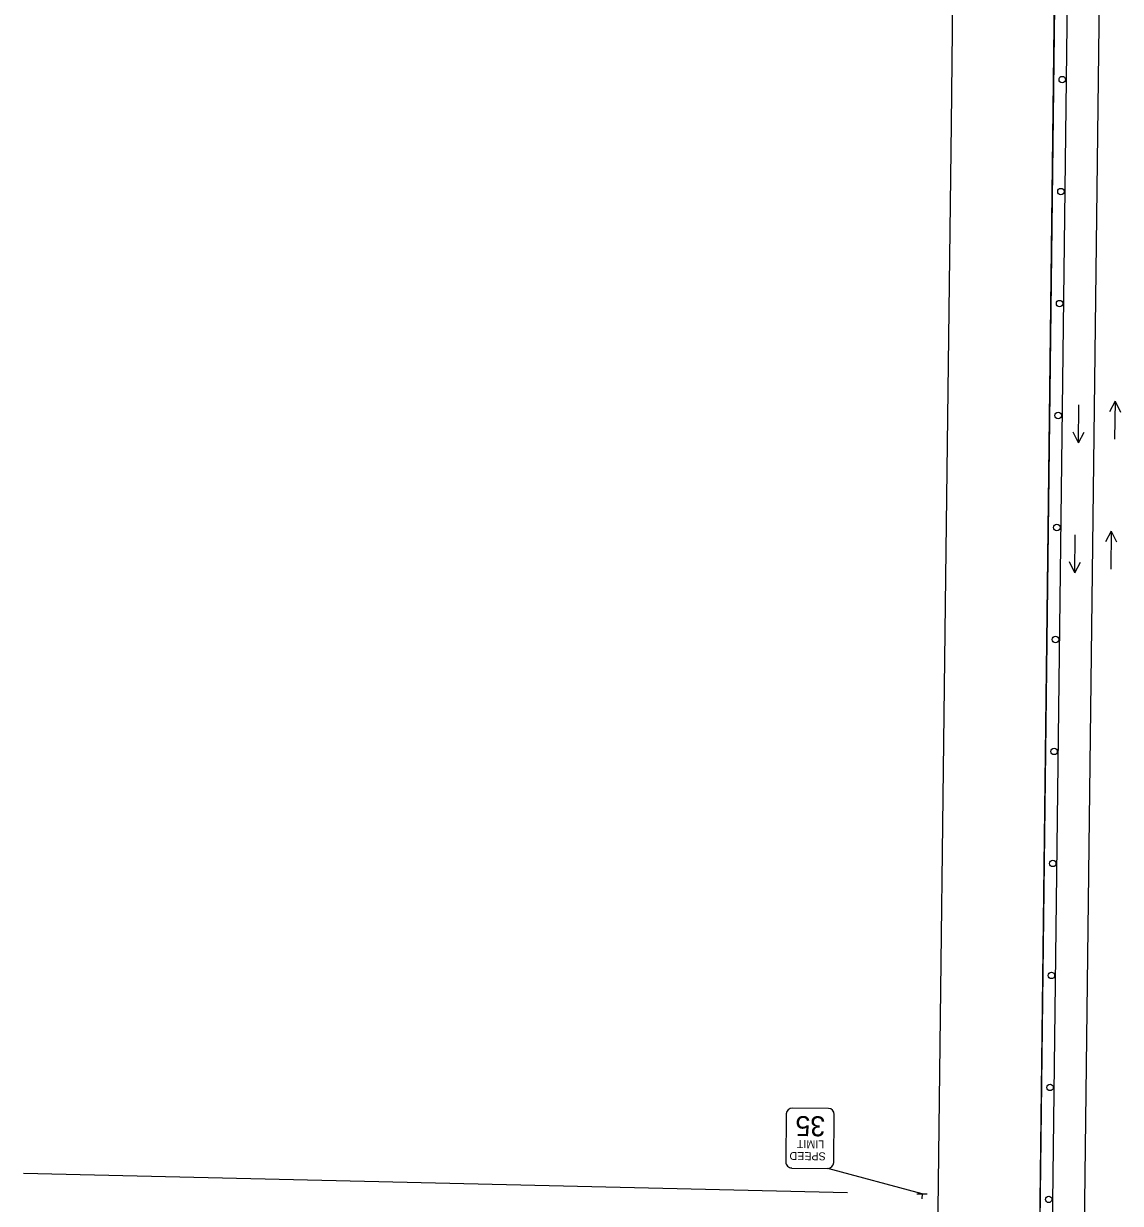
# Model space of a CAD drawing. Extents: x 1651568 to 1653044, y 601329 to 611807.
# Drawn here: x 1652241.2 to 1652584.1, y 607792.4 to 608161.1 of the extents above; entities that cross this region are included whole.
import ezdxf

# ---------------------------------------------------------------- set-up
doc = ezdxf.new("R2010")
doc.units = 0
for name, color, linetype in [('CM_Corridor_Design', 7, 'Continuous'), ('DT_X_Break_Line', 7, 'Continuous'), ('DT_X_Contour_Major', 7, 'Continuous'), ('GE_P_Alignment_500_Cardinal_Points', 7, 'Continuous'), ('MD_P_Drive_MatchLine', 7, 'Continuous'), ('PF_P_Grade_Line_RT', 7, 'Continuous'), ('PF_X_Ground_Line', 7, 'Continuous'), ('PV_P_EOP', 7, 'Continuous'), ('PV_X_EOP', 7, 'Continuous')]:
    doc.layers.add(name, color=color, linetype=linetype)

msp = doc.modelspace()

# ---------------------------------------------------------------- linework, layer by layer
at = {"layer": 'CM_Corridor_Design'}
for p, q in [((1652570.95, 608030.08), (1652571.08, 608041.94)), ((1652582.37, 608043.1), (1652580.61, 608039.74)), ((1652582.37, 608043.1), (1652582.24, 608031.24)), ((1652582.37, 608043.1), (1652584.05, 608039.71)), ((1652570.95, 608030.08), (1652569.27, 608033.47)), ((1652570.95, 608030.08), (1652572.71, 608033.44)), ((1652569.81, 607989.48), (1652569.94, 608001.34)), ((1652581.15, 608002.5), (1652579.39, 607999.14)), ((1652581.15, 608002.5), (1652581.02, 607990.64)), ((1652581.15, 608002.5), (1652582.84, 607999.11)), ((1652569.81, 607989.48), (1652568.13, 607992.87)), ((1652569.81, 607989.48), (1652571.57, 607992.83))]:
    msp.add_line(p, q, dxfattribs=at)
at = {"layer": 'DT_X_Break_Line'}
for centre in [(1652565.87, 608143.61), (1652565.45, 608108.61), (1652565.03, 608073.62), (1652564.61, 608038.62), (1652564.18, 608003.62), (1652563.76, 607968.62), (1652563.34, 607933.63), (1652562.91, 607898.63), (1652562.49, 607863.63), (1652562.07, 607828.63), (1652561.65, 607793.64)]:
    msp.add_circle(centre, 1, dxfattribs=at)
at = {"layer": 'DT_X_Contour_Major'}
msp.add_line((1652551.76, 607199.34), (1652567.38, 608491.59), dxfattribs=at)
for points in [[(1652520.46, 607301.97), (1652521.05, 607315.67), (1652521.05, 607315.61), (1652521.06, 607315.89), (1652521.05, 607315.67), (1652522.05, 607405.28), (1652522.05, 607405.32), (1652523.62, 607497.33), (1652523.6, 607516.01), (1652525.27, 607645.77), (1652525.48, 607668.54), (1652527.11, 607790.41), (1652527.11, 607790.42), (1652529.48, 607988.14), (1652531.24, 608129.69), (1652532.94, 608285.66), (1652534.22, 608392.25), (1652536.08, 608599.02), (1652568.71, 608598.61), (1652551.76, 607199.34), (1652540.01, 606229.06)], [(1652520.46, 607301.97), (1652521.05, 607315.67), (1652521.05, 607315.61), (1652521.06, 607315.89), (1652521.05, 607315.67), (1652522.05, 607405.28), (1652522.05, 607405.32), (1652523.62, 607497.33), (1652523.6, 607516.01), (1652525.27, 607645.77), (1652525.48, 607668.54), (1652527.11, 607790.41), (1652527.11, 607790.42), (1652529.48, 607988.14), (1652531.24, 608129.69), (1652532.94, 608285.66), (1652534.22, 608392.25), (1652536.08, 608599.02), (1652568.71, 608598.61), (1652551.76, 607199.34), (1652540.01, 606229.06)], [(1652527.11, 607790.41), (1652529.48, 607988.14), (1652531.24, 608129.69), (1652532.94, 608285.66), (1652534.22, 608392.25), (1652535.14, 608525.89)]]:
    msp.add_lwpolyline(points, dxfattribs=at)
at = {"layer": 'GE_P_Alignment_500_Cardinal_Points'}
msp.add_line((1652498.72, 607795.73), (1652241.24, 607801.7), dxfattribs=at)
at = {"layer": 'MD_P_Drive_MatchLine'}
msp.add_line((1652522.06, 607795.4), (1652492.57, 607803.33), dxfattribs=at)
at = {"layer": 'PF_P_Grade_Line_RT'}
for p, q in [((1652520.46, 607795.43), (1652523.66, 607795.36)), ((1652522.06, 607795.4), (1652522.03, 607793.8)), ((1652522.06, 607795.39), (1652522.06, 607795.39))]:
    msp.add_line(p, q, dxfattribs=at)
at = {"layer": 'PF_X_Ground_Line'}
for points in [[(1652492.77, 607822.08), (1652481.53, 607822.2)], [(1652479.63, 607820.35), (1652479.47, 607805.35)], [(1652494.46, 607805.18), (1652494.63, 607820.18)], [(1652481.32, 607803.45), (1652492.57, 607803.33)]]:
    msp.add_lwpolyline(points, dxfattribs=at)
for centre, start, end in [((1652481.5, 607820.33), 89.3709, 179.3709), ((1652492.75, 607820.2), 359.3709, 89.3709), ((1652481.34, 607805.33), 179.3709, 269.3709), ((1652492.59, 607805.21), 269.3709, 359.3709)]:
    msp.add_arc(centre, 1.87, start, end, dxfattribs=at)
at = {"layer": 'PV_P_EOP'}
msp.add_line((1652556.99, 607300.84), (1652572.67, 608598.56), dxfattribs=at)
at = {"layer": 'PV_X_EOP'}
msp.add_line((1652566.99, 607300.72), (1652582.67, 608598.44), dxfattribs=at)

# ---------------------------------------------------------------- texts
at = {"layer": 'PF_X_Ground_Line'}
for s, height, p in [('35', 6.25, (1652491.82, 607819.59)), ('LIMIT', 2.5, (1652491.49, 607812.09)), ('SPEED', 2.5, (1652491.97, 607808.34))]:
    msp.add_text(s, height=height, rotation=179.3709, dxfattribs=at).set_placement(p)

doc.saveas('drawing.dxf')
